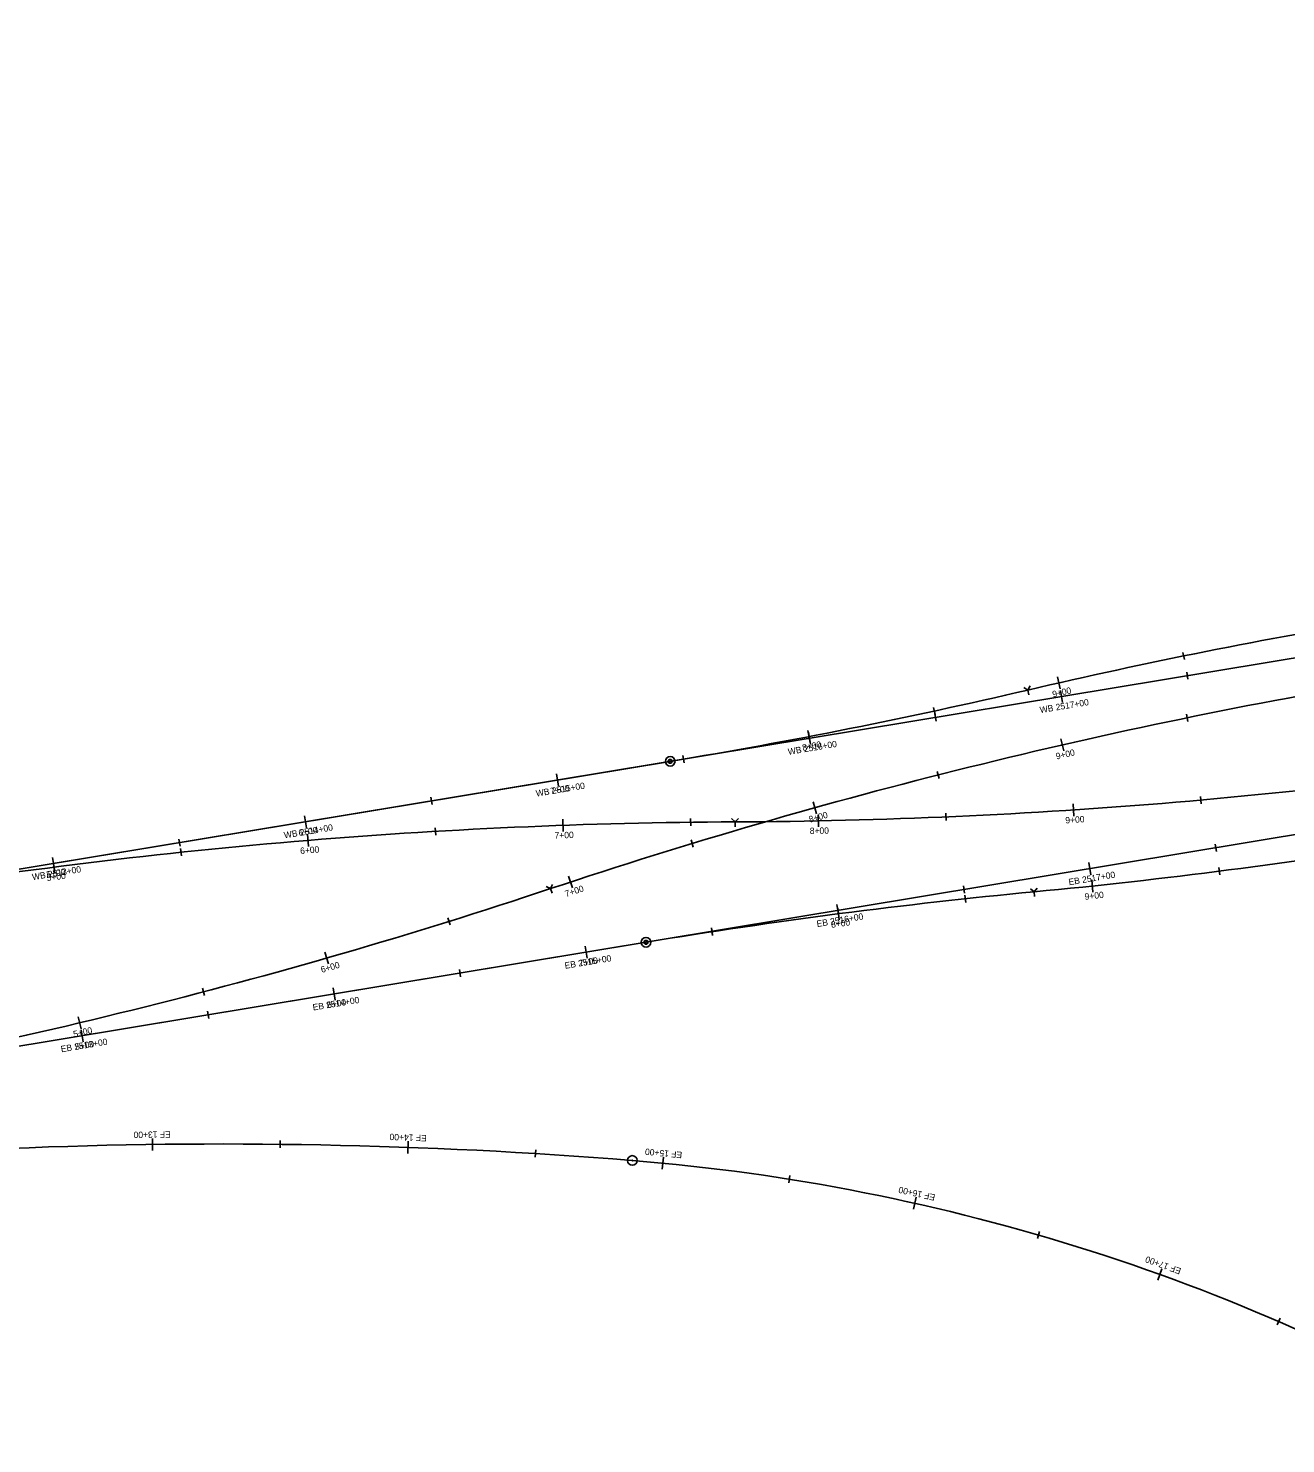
# Model space of a CAD drawing. Extents: x 950864 to 953360, y 1126381 to 1128045.
# Drawn here: x 951356 to 951848, y 1126976 to 1127530 of the extents above; entities that cross this region are included whole.
import ezdxf

# ---------------------------------------------------------------- set-up
doc = ezdxf.new("R2010")
doc.units = 0
for name, color, linetype in [('Existing', 7, 'Continuous'), ('LFILL_P', 7, 'Continuous'), ('North Crossover', 7, 'Continuous')]:
    doc.layers.add(name, color=color, linetype=linetype)

msp = doc.modelspace()

# ---------------------------------------------------------------- linework, layer by layer
at = {"layer": 'Existing'}
for p, q in [((950872.52, 1127121.15), (953338.85, 1127530.05)), ((950883.69, 1127053.72), (953350.03, 1127462.62))]:
    msp.add_line(p, q, dxfattribs=at)
for points in [[(951809.49, 1127277.95), (951809.96, 1127275.11)], [(951760, 1127270.72), (951760.79, 1127265.98)], [(951710.83, 1127261.6), (951711.3, 1127258.75)], [(951661.35, 1127254.36), (951662.13, 1127249.63)], [(951612.18, 1127245.24), (951612.65, 1127242.4)], [(951562.7, 1127238.01), (951563.48, 1127233.27)], [(951513.53, 1127228.88), (951514, 1127226.04)], [(951464.04, 1127221.65), (951464.83, 1127216.92)], [(951414.87, 1127212.53), (951415.34, 1127209.69)], [(951820.67, 1127210.52), (951821.14, 1127207.68)], [(951365.39, 1127205.3), (951366.17, 1127200.56)], [(951771.18, 1127203.29), (951771.97, 1127198.56)], [(951722.01, 1127194.17), (951722.48, 1127191.33)], [(951672.53, 1127186.94), (951673.31, 1127182.2)], [(951623.36, 1127177.81), (951623.83, 1127174.97)], [(951573.88, 1127170.58), (951574.66, 1127165.85)], [(951524.71, 1127161.46), (951525.18, 1127158.61)], [(951475.22, 1127154.22), (951476.01, 1127149.49)], [(951426.05, 1127145.1), (951426.52, 1127142.26)], [(951376.57, 1127137.87), (951377.35, 1127133.13)], [(951404.5, 1127095.31), (951404.57, 1127090.51)], [(951454.55, 1127094.42), (951454.52, 1127091.54)], [(951504.61, 1127094.19), (951504.43, 1127089.39)], [(951554.55, 1127090.79), (951554.37, 1127087.91)], [(951604.54, 1127087.99), (951604.09, 1127083.21)], [(951654.13, 1127080.71), (951653.68, 1127077.86)], [(951703.53, 1127072.23), (951702.48, 1127067.54)], [(951751.83, 1127058.82), (951751.02, 1127056.05)], [(951799.78, 1127044.25), (951798.16, 1127039.73)], [(951846.03, 1127024.92), (951844.88, 1127022.28)]]:
    msp.add_lwpolyline(points, dxfattribs=at)
for radius in [1.89, 0.154]:
    msp.add_circle((951592.38, 1127086.65), radius, dxfattribs=at)
for centre, radius, start, end in [((951432.14, 1125099.1), 1994, 85.39079, 99.4135), ((951528.09, 1126289.24), 800, 59.10473, 85.39079)]:
    msp.add_arc(centre, radius, start, end, dxfattribs=at)
at = {"layer": 'LFILL_P'}
for p, q in [((951632.61, 1127219.25), (951631.28, 1127220.58)), ((951633.94, 1127220.59), (951632.61, 1127219.25)), ((951632.61, 1127219.25), (951632.62, 1127217.37)), ((951749.73, 1127191.86), (951748.27, 1127193.07)), ((951750.93, 1127193.32), (951749.73, 1127191.86)), ((951749.73, 1127191.86), (951749.9, 1127189.99)), ((950883.69, 1127053.72), (951597.75, 1127172.11))]:
    msp.add_line(p, q, dxfattribs=at)
for points in [[(951814.86, 1127229.23), (951815.11, 1127226.36)], [(951715.15, 1127222.65), (951715.27, 1127219.77)], [(951764.98, 1127226.32), (951765.29, 1127221.53)], [(951515.23, 1127216.97), (951515.4, 1127214.09)], [(951565.17, 1127220.29), (951565.34, 1127215.49)], [(951615.22, 1127220.54), (951615.26, 1127217.66)], [(951665.19, 1127222.05), (951665.28, 1127217.25)], [(951465.24, 1127214.4), (951465.63, 1127209.62)], [(951415.51, 1127208.78), (951415.81, 1127205.91)], [(951365.69, 1127203.91), (951366.3, 1127199.15)], [(951822, 1127201.36), (951822.37, 1127198.51)], [(951772.27, 1127196.53), (951772.77, 1127191.75)], [(951722.62, 1127190.58), (951722.93, 1127187.72)], [(951672.81, 1127185.64), (951673.43, 1127180.88)], [(951623.4, 1127177.66), (951623.84, 1127174.81)], [(951573.88, 1127170.58), (951574.66, 1127165.85)], [(951524.71, 1127161.46), (951525.18, 1127158.61)], [(951475.22, 1127154.22), (951476.01, 1127149.49)], [(951426.05, 1127145.1), (951426.52, 1127142.26)], [(951376.57, 1127137.87), (951377.35, 1127133.13)]]:
    msp.add_lwpolyline(points, dxfattribs=at)
for centre, radius in [((951632.61, 1127219.25), 0.154), ((951749.73, 1127191.86), 0.154), ((951597.75, 1127172.11), 1.88), ((951597.75, 1127172.11), 0.747), ((951597.75, 1127172.11), 0.156)]:
    msp.add_circle(centre, radius, dxfattribs=at)
for centre, radius, start, end in [((951622.6, 1129384.23), 2165, 270.26513, 279.4135), ((951642.63, 1125054.28), 2165, 90.26513, 99.4135), ((951543.67, 1129371.14), 2189, 275.4013, 279.4135), ((951955.78, 1125012.58), 2189, 95.4013, 99.4135)]:
    msp.add_arc(centre, radius, start, end, dxfattribs=at)
at = {"layer": 'North Crossover'}
for p, q in [((951748.23, 1127272.49), (951747.24, 1127270.89)), ((951747.24, 1127270.89), (951745.64, 1127271.88)), ((951747.24, 1127270.89), (951747.66, 1127269.06)), ((950872.52, 1127121.15), (951607.23, 1127242.96)), ((951561.19, 1127194.79), (951560.35, 1127193.1)), ((951560.35, 1127193.1), (951558.67, 1127193.94)), ((951560.35, 1127193.1), (951560.95, 1127191.31))]:
    msp.add_line(p, q, dxfattribs=at)
for points in [[(951807.97, 1127285.64), (951808.55, 1127282.82)], [(951758.85, 1127276.03), (951759.92, 1127271.35)], [(951710.31, 1127264.07), (951710.92, 1127261.26)], [(951809.33, 1127261.42), (951809.91, 1127258.6)], [(951661.17, 1127255.04), (951662.07, 1127250.33)], [(951760.23, 1127251.73), (951761.3, 1127247.05)], [(951612.18, 1127245.24), (951612.65, 1127242.4)], [(951711.81, 1127239.03), (951712.52, 1127236.24)], [(951562.7, 1127238.01), (951563.48, 1127233.27)], [(951513.53, 1127228.88), (951514, 1127226.04)], [(951663.21, 1127227.08), (951664.5, 1127222.45)], [(951464.04, 1127221.65), (951464.83, 1127216.92)], [(951414.87, 1127212.53), (951415.34, 1127209.69)], [(951615.43, 1127212.16), (951616.27, 1127209.41)], [(951365.39, 1127205.3), (951366.17, 1127200.56)], [(951567.43, 1127197.98), (951568.93, 1127193.42)], [(951520.19, 1127181.65), (951521.05, 1127178.9)], [(951472.06, 1127168.23), (951473.38, 1127163.62)], [(951424.14, 1127154.08), (951424.87, 1127151.3)], [(951375.45, 1127142.9), (951376.56, 1127138.23)]]:
    msp.add_lwpolyline(points, dxfattribs=at)
for centre, radius in [((951747.24, 1127270.89), 0.154), ((951607.23, 1127242.96), 1.88), ((951607.23, 1127242.96), 0.747), ((951607.23, 1127242.96), 0.156), ((951560.35, 1127193.1), 0.154)]:
    msp.add_circle(centre, radius, dxfattribs=at)
for centre, radius, start, end in [((952245.27, 1125139.3), 2189, 99.4135, 103.15104), ((952245.27, 1125139.3), 2165, 99.4135, 108.44308), ((951249.2, 1129402.48), 2189, 279.4135, 283.15104), ((950875.43, 1129246.9), 2165, 279.4135, 288.44308)]:
    msp.add_arc(centre, radius, start, end, dxfattribs=at)

# ---------------------------------------------------------------- texts
at = {"layer": 'Existing'}
for s, rotation, p in [('WB 2517+00', 9.4135, (951752.15, 1127261.83)), ('WB 2516+00', 9.4135, (951653.52, 1127245.48)), ('WB 2515+00', 9.4135, (951554.85, 1127229.12)), ('WB 2514+00', 9.4135, (951456.19, 1127212.76)), ('WB 2513+00', 9.4135, (951357.57, 1127196.41)), ('EB 2517+00', 9.4135, (951763.41, 1127194.41)), ('EB 2516+00', 9.4135, (951664.78, 1127178.06)), ('EB 2515+00', 9.4135, (951566.11, 1127161.7)), ('EB 2514+00', 9.4135, (951467.45, 1127145.35)), ('EB 2513+00', 9.4135, (951368.83, 1127129)), ('EF 13+00', 180.7933, (951411.66, 1127098.1)), ('EF 14+00', 177.9199, (951511.94, 1127096.61)), ('EF 15+00', 174.5325, (951612, 1127089.98)), ('EF 16+00', 167.3706, (951711.16, 1127073.27)), ('EF 17+00', 160.2086, (951807.5, 1127044.32))]:
    msp.add_text(s, height=2.496, rotation=rotation, dxfattribs=at).set_placement(p)
at = {"layer": 'LFILL_P'}
for s, rotation, p in [('8+00', 1.1285, (951661.88, 1127214.49)), ('9+00', 3.775, (951762.02, 1127218.62)), ('7+00', 2.0482, (951561.98, 1127212.68)), ('6+00', 4.6946, (951462.43, 1127206.66)), ('5+00', 7.3411, (951363.22, 1127196.04)), ('9+00', 6.001, (951769.62, 1127188.72)), ('8+00', 7.419, (951670.35, 1127177.77)), ('7+00', 9.4135, (951571.69, 1127162.63)), ('6+00', 9.4135, (951473.06, 1127146.28)), ('5+00', 9.4135, (951374.39, 1127129.92))]:
    msp.add_text(s, height=2.496, rotation=rotation, dxfattribs=at).set_placement(p)
at = {"layer": 'North Crossover'}
for s, rotation, p in [('9+00', 12.8247, (951757.14, 1127267.96)), ('8+00', 10.8599, (951659.18, 1127247.04)), ('9+00', 12.9319, (951758.53, 1127243.66)), ('7+00', 9.4135, (951560.51, 1127230.06)), ('8+00', 15.5783, (951661.89, 1127218.94)), ('6+00', 9.4135, (951461.88, 1127213.7)), ('5+00', 9.4135, (951363.21, 1127197.35)), ('7+00', 18.2248, (951566.49, 1127189.78)), ('6+00', 16.0149, (951470.82, 1127160.09)), ('5+00', 13.3685, (951373.82, 1127134.82))]:
    msp.add_text(s, height=2.496, rotation=rotation, dxfattribs=at).set_placement(p)

doc.saveas('drawing.dxf')
